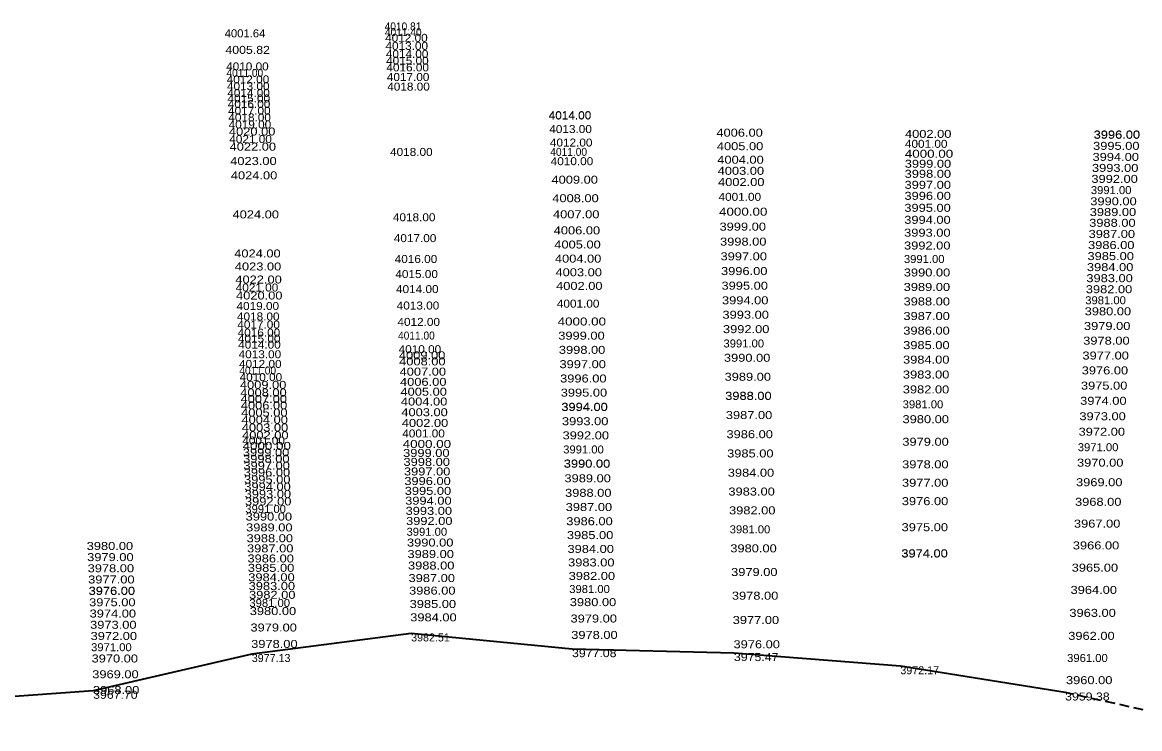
# Model space of a CAD drawing. Extents: x 49942 to 56479, y 47140 to 53283.
# Drawn here: x 53343 to 54041, y 49867 to 50309 of the extents above; entities that cross this region are included whole.
import ezdxf

# ---------------------------------------------------------------- set-up
doc = ezdxf.new("R2010")
doc.units = 0
doc.header["$LTSCALE"] = 2
doc.linetypes.add('MEDIUM_DASHED', pattern=[4.5, 3, -1.5])
doc.layers.add('29', color=7, linetype='Continuous')
doc.layers.add('59', color=7, linetype='Continuous', lineweight=35)

msp = doc.modelspace()

# ---------------------------------------------------------------- linework, layer by layer
at = {"layer": '59'}
for p, q in [((53586.164, 49926.471), (53486.628, 49913.58)), ((53686.683, 49916.638), (53586.164, 49926.471)), ((53486.628, 49913.58), (53387.529, 49890.602)), ((53787.836, 49914.193), (53686.683, 49916.638)), ((53891.806, 49905.923), (53787.836, 49914.193)), ((53994.743, 49889.532), (53891.806, 49905.923)), ((53387.529, 49890.602), (53287.754, 49883.256))]:
    msp.add_line(p, q, dxfattribs=at)
at = {"layer": '59', "linetype": 'MEDIUM_DASHED'}
msp.add_line((54096.16, 49866.921), (53994.743, 49889.532), dxfattribs=at)

# ---------------------------------------------------------------- texts
at = {"layer": '29'}
for s, width, p in [('4001.64', 1.05, (53469.718, 50299.148)), ('4010.81', 0.95, (53569.624, 50303.474)), ('4011.40', 0.95, (53569.778, 50299.923)), ('4012.00', 1.1, (53569.932, 50296.371)), ('4013.00', 1.1, (53570.151, 50291.321)), ('4005.82', 1.15, (53470.165, 50288.817)), ('4014.00', 1.1, (53570.369, 50286.271)), ('4010.00', 1.1, (53470.613, 50278.486)), ('4015.00', 1.1, (53570.551, 50282.075)), ('4016.00', 1.1, (53570.733, 50277.88)), ('4011.00', 0.95, (53470.789, 50274.423)), ('4012.00', 1.1, (53470.964, 50270.361)), ('4017.00', 1.1, (53570.993, 50271.865)), ('4013.00', 1.1, (53471.147, 50266.144)), ('4018.00', 1.1, (53571.253, 50265.849)), ('4014.00', 1.1, (53471.33, 50261.927)), ('4015.00', 1.1, (53471.48, 50258.452)), ('4016.00', 1.1, (53471.631, 50254.976)), ('4017.00', 1.1, (53471.812, 50250.79)), ('4018.00', 1.1, (53471.993, 50246.6)), ('4014.00', 1.1, (53672.119, 50248.03)), ('4014.00', 1.1, (53672.123, 50247.921)), ('4014.00', 1.1, (53672.129, 50247.783)), ('4019.00', 1.1, (53472.184, 50242.195)), ('4020.00', 1.2, (53472.375, 50237.79)), ('4013.00', 1.1, (53672.495, 50239.331)), ('4006.00', 1.2, (53776.873, 50237.063)), ('4002.00', 1.2, (53894.692, 50236.293)), ('3996.00', 1.2, (54012.543, 50235.737)), ('3996.00', 1.2, (54012.549, 50235.85)), ('3996.00', 1.2, (54012.554, 50235.942)), ('4021.00', 1.1, (53472.58, 50233.046)), ('4022.00', 1.2, (53472.785, 50228.302)), ('4012.00', 1.1, (53672.861, 50230.878)), ('4005.00', 1.2, (53777.155, 50228.605)), ('4001.00', 1.1, (53894.639, 50230.085)), ('3995.00', 1.2, (54012.193, 50228.82)), ('4018.00', 1.1, (53573.022, 50225.005)), ('4011.00', 0.95, (53673.113, 50225.055)), ('4000.00', 1.25, (53894.585, 50223.877)), ('3994.00', 1.2, (54011.842, 50221.902)), ('4023.00', 1.2, (53473.174, 50219.336)), ('4010.00', 1.1, (53673.366, 50219.233)), ('4004.00', 1.2, (53777.438, 50220.147)), ('3999.00', 1.2, (53894.532, 50217.611)), ('3993.00', 1.2, (54011.494, 50215.031)), ('4024.00', 1.2, (53473.562, 50210.371)), ('4009.00', 1.2, (53673.867, 50207.656)), ('4003.00', 1.2, (53777.67, 50213.209)), ('3998.00', 1.2, (53894.478, 50211.346)), ('3992.00', 1.2, (54011.146, 50208.159)), ('4002.00', 1.2, (53777.905, 50206.194)), ('3997.00', 1.2, (53894.418, 50204.46)), ('3991.00', 1.05, (54010.791, 50201.157)), ('4008.00', 1.2, (53674.368, 50196.079)), ('4001.00', 1.1, (53778.214, 50196.943)), ('3996.00', 1.2, (53894.359, 50197.574)), ('3990.00', 1.2, (54010.436, 50194.154)), ('4000.00', 1.25, (53778.524, 50187.664)), ('3995.00', 1.2, (53894.294, 50190.072)), ('3989.00', 1.2, (54010.095, 50187.424)), ('4024.00', 1.2, (53474.619, 50185.958)), ('4018.00', 1.1, (53574.79, 50184.162)), ('4007.00', 1.2, (53674.803, 50186.028)), ('3994.00', 1.2, (53894.23, 50182.57)), ('3988.00', 1.2, (54009.754, 50180.694)), ('4006.00', 1.2, (53675.238, 50175.976)), ('3999.00', 1.2, (53778.837, 50178.304)), ('3993.00', 1.2, (53894.161, 50174.534)), ('3987.00', 1.2, (54009.401, 50173.743)), ('4017.00', 1.1, (53575.355, 50171.124)), ('4005.00', 1.2, (53675.621, 50167.143)), ('3998.00', 1.2, (53779.15, 50168.945)), ('3992.00', 1.2, (53894.092, 50166.498)), ('3986.00', 1.2, (54009.049, 50166.793)), ('4024.00', 1.2, (53475.676, 50161.546)), ('3997.00', 1.2, (53779.458, 50159.734)), ('3985.00', 1.2, (54008.699, 50159.894)), ('4023.00', 1.2, (53476.029, 50153.396)), ('4016.00', 1.1, (53575.919, 50158.086)), ('4004.00', 1.2, (53676.003, 50158.311)), ('3991.00', 1.05, (53894.019, 50158.073)), ('3984.00', 1.2, (54008.35, 50152.995)), ('4022.00', 1.2, (53476.381, 50145.246)), ('4015.00', 1.1, (53576.327, 50148.671)), ('4003.00', 1.2, (53676.373, 50149.776)), ('3996.00', 1.2, (53779.766, 50150.524)), ('3990.00', 1.2, (53893.946, 50149.648)), ('3983.00', 1.2, (54008, 50146.088)), ('4021.00', 1.1, (53476.598, 50140.243)), ('4014.00', 1.1, (53576.735, 50139.255)), ('4002.00', 1.2, (53676.742, 50141.242)), ('3995.00', 1.2, (53780.072, 50141.386)), ('3989.00', 1.2, (53893.869, 50140.595)), ('3982.00', 1.2, (54007.65, 50139.18)), ('4020.00', 1.2, (53476.815, 50135.239)), ('3994.00', 1.2, (53780.377, 50132.249)), ('3988.00', 1.2, (53893.791, 50131.542)), ('3981.00', 1.05, (54007.3, 50132.279)), ('4019.00', 1.1, (53477.098, 50128.693)), ('4013.00', 1.1, (53577.179, 50128.999)), ('4001.00', 1.1, (53677.222, 50130.171)), ('3980.00', 1.2, (54006.95, 50125.378)), ('4018.00', 1.1, (53477.382, 50122.146)), ('4017.00', 1.1, (53477.601, 50117.087)), ('4012.00', 1.1, (53577.623, 50118.743)), ('4000.00', 1.25, (53677.705, 50119.006)), ('3993.00', 1.2, (53780.679, 50123.236)), ('3987.00', 1.2, (53893.712, 50122.422)), ('4016.00', 1.1, (53477.82, 50112.029)), ('4011.00', 0.95, (53577.992, 50110.206)), ('3999.00', 1.2, (53678.089, 50110.138)), ('3992.00', 1.2, (53780.98, 50114.222)), ('3986.00', 1.2, (53893.634, 50113.302)), ('3979.00', 1.2, (54006.485, 50116.198)), ('4015.00', 1.1, (53477.982, 50108.281)), ('4014.00', 1.1, (53478.144, 50104.534)), ('3991.00', 1.05, (53781.279, 50105.269)), ('3985.00', 1.2, (53893.556, 50104.23)), ('3978.00', 1.2, (54006.019, 50107.019)), ('4013.00', 1.1, (53478.405, 50098.506)), ('4010.00', 1.1, (53578.362, 50101.668)), ('4009.00', 1.2, (53578.527, 50097.854)), ('3998.00', 1.2, (53678.473, 50101.27)), ('3990.00', 1.2, (53781.579, 50096.317)), ('3977.00', 1.2, (54005.548, 50097.716)), ('4012.00', 1.1, (53478.666, 50092.476)), ('4008.00', 1.2, (53578.692, 50094.041)), ('3997.00', 1.2, (53678.861, 50092.317)), ('3984.00', 1.2, (53893.477, 50095.158)), ('4011.00', 0.95, (53478.845, 50088.353)), ('4010.00', 1.1, (53479.023, 50084.229)), ('4007.00', 1.2, (53578.969, 50087.655)), ('3996.00', 1.2, (53679.248, 50083.364)), ('3989.00', 1.2, (53781.976, 50084.446)), ('3983.00', 1.2, (53893.397, 50085.844)), ('3976.00', 1.2, (54005.076, 50088.414)), ('4009.00', 1.2, (53479.233, 50079.392)), ('4006.00', 1.2, (53579.245, 50081.268)), ('4005.00', 1.2, (53579.512, 50075.117)), ('3982.00', 1.2, (53893.317, 50076.53)), ('3975.00', 1.2, (54004.595, 50078.917)), ('4008.00', 1.2, (53479.442, 50074.556)), ('4007.00', 1.2, (53479.615, 50070.566)), ('4004.00', 1.2, (53579.778, 50068.965)), ('3995.00', 1.2, (53679.631, 50074.53)), ('3988.00', 1.2, (53782.373, 50072.576)), ('3988.00', 1.2, (53782.375, 50072.506)), ('3988.00', 1.2, (53782.377, 50072.434)), ('3974.00', 1.2, (54004.114, 50069.421)), ('4006.00', 1.2, (53479.788, 50066.576)), ('4005.00', 1.2, (53479.983, 50062.06)), ('4003.00', 1.2, (53580.068, 50062.269)), ('3994.00', 1.2, (53680.013, 50065.695)), ('3994.00', 1.2, (53680.017, 50065.607)), ('3994.00', 1.2, (53680.021, 50065.514)), ('3981.00', 1.05, (53893.237, 50067.225)), ('4004.00', 1.2, (53480.179, 50057.545)), ('4002.00', 1.2, (53580.358, 50055.573)), ('3993.00', 1.2, (53680.405, 50056.654)), ('3987.00', 1.2, (53782.776, 50060.508)), ('3980.00', 1.2, (53893.157, 50057.92)), ('3973.00', 1.2, (54003.624, 50059.752)), ('4003.00', 1.2, (53480.388, 50052.704)), ('4002.00', 1.2, (53480.598, 50047.862)), ('4001.00', 1.1, (53580.642, 50049.015)), ('3992.00', 1.2, (53680.788, 50047.794)), ('3986.00', 1.2, (53783.177, 50048.529)), ('3972.00', 1.2, (54003.134, 50050.084)), ('4001.00', 1.1, (53480.742, 50044.536)), ('4000.00', 1.25, (53480.886, 50041.209)), ('4000.00', 1.25, (53580.927, 50042.422)), ('3979.00', 1.2, (53893.035, 50043.811)), ('3971.00', 1.05, (54002.644, 50040.418)), ('3999.00', 1.2, (53481.06, 50037.186)), ('3998.00', 1.2, (53481.234, 50033.162)), ('3999.00', 1.2, (53581.17, 50036.818)), ('3991.00', 1.05, (53681.169, 50038.999)), ('3985.00', 1.2, (53783.579, 50036.497)), ('3997.00', 1.2, (53481.418, 50028.921)), ('3998.00', 1.2, (53581.412, 50031.214)), ('3990.00', 1.2, (53681.55, 50030.204)), ('3990.00', 1.2, (53681.553, 50030.127)), ('3990.00', 1.2, (53681.556, 50030.05)), ('3978.00', 1.2, (53892.914, 50029.702)), ('3970.00', 1.2, (54002.154, 50030.751)), ('3996.00', 1.2, (53481.602, 50024.679)), ('3995.00', 1.2, (53481.795, 50020.21)), ('3997.00', 1.2, (53581.671, 50025.236)), ('3996.00', 1.2, (53581.93, 50019.259)), ('3989.00', 1.2, (53681.95, 50020.965)), ('3984.00', 1.2, (53783.982, 50024.464)), ('3994.00', 1.2, (53481.989, 50015.742)), ('3995.00', 1.2, (53582.196, 50013.109)), ('3988.00', 1.2, (53682.343, 50011.881)), ('3983.00', 1.2, (53784.375, 50012.688)), ('3977.00', 1.2, (53892.815, 50018.188)), ('3969.00', 1.2, (54001.533, 50018.506)), ('3993.00', 1.2, (53482.188, 50011.124)), ('3992.00', 1.2, (53482.388, 50006.506)), ('3994.00', 1.2, (53582.463, 50006.96)), ('3976.00', 1.2, (53892.716, 50006.673)), ('3968.00', 1.2, (54000.913, 50006.261)), ('3991.00', 1.05, (53482.594, 50001.766)), ('3993.00', 1.2, (53582.737, 50000.622)), ('3987.00', 1.2, (53682.728, 50002.998)), ('3982.00', 1.2, (53784.769, 50000.912)), ('3990.00', 1.2, (53482.799, 49997.025)), ('3992.00', 1.2, (53583.011, 49994.285)), ('3986.00', 1.2, (53683.112, 49994.116)), ('3967.00', 1.2, (54000.222, 49992.629)), ('3989.00', 1.2, (53483.092, 49990.254)), ('3991.00', 1.05, (53583.303, 49987.539)), ('3985.00', 1.2, (53683.487, 49985.455)), ('3981.00', 1.05, (53785.166, 49989.042)), ('3975.00', 1.2, (53892.576, 49990.388)), ('3980.00', 1.2, (53383.501, 49978.656)), ('3988.00', 1.2, (53483.385, 49983.482)), ('3987.00', 1.2, (53483.659, 49977.161)), ('3990.00', 1.2, (53583.595, 49980.793)), ('3980.00', 1.2, (53785.563, 49977.172)), ('3966.00', 1.2, (53999.531, 49978.998)), ('3979.00', 1.2, (53383.802, 49971.683)), ('3986.00', 1.2, (53483.933, 49970.84)), ('3989.00', 1.2, (53583.906, 49973.615)), ('3984.00', 1.2, (53683.862, 49976.794)), ('3974.00', 1.2, (53892.434, 49973.931)), ('3974.00', 1.2, (53892.435, 49974.103)), ('3974.00', 1.2, (53892.435, 49974.036)), ('3978.00', 1.2, (53384.104, 49964.71)), ('3985.00', 1.2, (53484.187, 49964.965)), ('3988.00', 1.2, (53584.217, 49966.436)), ('3983.00', 1.2, (53684.228, 49968.356)), ('3965.00', 1.2, (53998.826, 49965.09)), ('3977.00', 1.2, (53384.408, 49957.694)), ('3984.00', 1.2, (53484.441, 49959.089)), ('3987.00', 1.2, (53584.557, 49958.587)), ('3982.00', 1.2, (53684.593, 49959.918)), ('3979.00', 1.2, (53786.058, 49962.366)), ('3976.00', 1.2, (53384.712, 49950.678)), ('3976.00', 1.2, (53384.716, 49950.588)), ('3976.00', 1.2, (53384.72, 49950.498)), ('3983.00', 1.2, (53484.679, 49953.596)), ('3986.00', 1.2, (53584.897, 49950.738)), ('3981.00', 1.05, (53684.948, 49951.728)), ('3964.00', 1.2, (53998.121, 49951.182)), ('3975.00', 1.2, (53385.025, 49943.452)), ('3982.00', 1.2, (53484.917, 49948.102)), ('3981.00', 1.05, (53485.137, 49943.025)), ('3985.00', 1.2, (53585.259, 49942.375)), ('3980.00', 1.2, (53685.302, 49943.538)), ('3978.00', 1.2, (53786.553, 49947.561)), ('3974.00', 1.2, (53385.33, 49936.406)), ('3980.00', 1.2, (53485.357, 49937.948)), ('3963.00', 1.2, (53997.393, 49936.822)), ('3973.00', 1.2, (53385.634, 49929.387)), ('3984.00', 1.2, (53585.621, 49934.013)), ('3979.00', 1.2, (53685.746, 49933.286)), ('3977.00', 1.2, (53787.061, 49932.376)), ('3972.00', 1.2, (53385.938, 49922.367)), ('3979.00', 1.2, (53485.802, 49927.677)), ('3978.00', 1.2, (53686.19, 49923.033)), ('3962.00', 1.2, (53996.665, 49922.461)), ('3971.00', 1.05, (53386.242, 49915.339)), ('3978.00', 1.2, (53486.246, 49917.406)), ('3976.00', 1.2, (53787.569, 49917.191)), ('3970.00', 1.2, (53386.546, 49908.31)), ('3977.08', 1.15, (53686.683, 49911.638)), ('3975.47', 1.15, (53787.836, 49909.193)), ('3961.00', 1.05, (53995.963, 49908.609)), ('3969.00', 1.2, (53386.974, 49898.437)), ('3960.00', 1.2, (53995.261, 49894.756)), ('3968.00', 1.2, (53387.401, 49888.564)), ('3967.70', 1.15, (53387.529, 49885.602)), ('3959.38', 1.15, (53994.743, 49884.532))]:
    msp.add_text(s, height=5, dxfattribs=dict(at, width=width)).set_placement(p)
for s, p in [('3982.51', (53586.164, 49921.471)), ('3977.13', (53486.628, 49908.58)), ('3972.17', (53891.806, 49900.923))]:
    msp.add_text(s, height=5, dxfattribs=at).set_placement(p)

doc.saveas('drawing.dxf')
